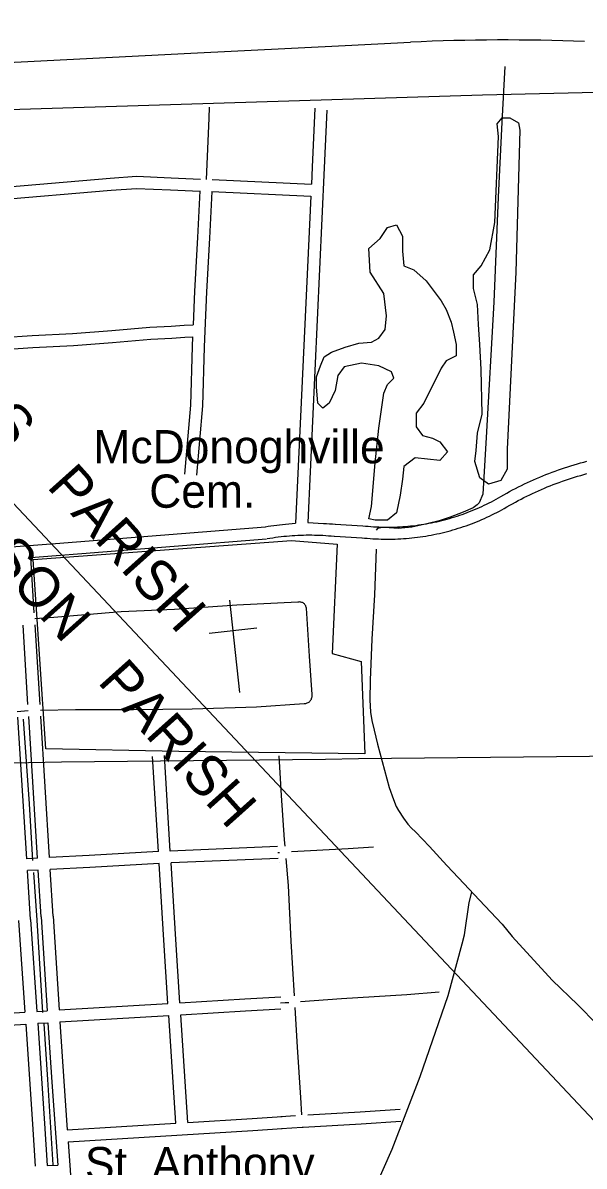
# Model space of a CAD drawing. Extents: x 3677843 to 3715951, y 511991 to 537744.
# Drawn here: x 3687711 to 3689113, y 522520 to 525377 of the extents above; entities that cross this region are included whole.
import ezdxf

# ---------------------------------------------------------------- set-up
doc = ezdxf.new("R2010")
doc.units = 0
for name, color, linetype in [('V-BLDG-IDEN', 7, 'Continuous'), ('V-GRID-MAJR', 7, 'Continuous'), ('V-ROAD-CNTR', 7, 'Continuous'), ('V-SITE-OTLN', 7, 'Continuous'), ('V-SITE-OTLN-IDEN', 7, 'Continuous'), ('V-SITE-VEGE', 7, 'Continuous'), ('V-TOPO-BNDY', 7, 'Continuous'), ('V-TOPO-GNAM-IDEN', 7, 'Continuous'), ('V-TOPO-SHOR', 7, 'Continuous')]:
    doc.layers.add(name, color=color, linetype=linetype)

msp = doc.modelspace()

# ---------------------------------------------------------------- linework, layer by layer
at = {"layer": 'V-GRID-MAJR'}
msp.add_spline([(3682033.6, 523465.9), (3687312.3, 523524.6), (3697869.7, 523644.4)], degree=3, dxfattribs=at)
at = {"layer": 'V-ROAD-CNTR'}
for points in [[(3687004.5, 525244), (3688130.3, 525301.7), (3688516.1, 525320.9), (3688678.9, 525328.8)], [(3689770.8, 525207.3), (3689688.8, 525210.6), (3689500.8, 525212), (3688859.6, 525196.6), (3686680.3, 525129.5)], [(3688176.4, 525166.3), (3688175.7, 525138.9), (3688168.9, 524986.1)], [(3688440.1, 525164.3), (3688433.5, 525016.5), (3688431.5, 524974.4)], [(3688469.9, 525158.9), (3688463.5, 525015.2), (3688422.4, 524128.4)], [(3687634.7, 524964.2), (3687929, 524989.3), (3687994.2, 524993.8), (3688080.9, 524990.4), (3688154.5, 524987)], [(3687636.8, 524934.3), (3687931.3, 524959.3), (3687994.6, 524963.7), (3688079.6, 524960.4), (3688153.1, 524957)], [(3688183.8, 524985.7), (3688431.5, 524974.4)], [(3688152.6, 524957.3), (3688147.1, 524840.6), (3688139.9, 524706.6), (3688136.3, 524622.6)], [(3688182.6, 524955.8), (3688177.1, 524839.1), (3688169.9, 524705.1), (3688165.6, 524607.6), (3688163.9, 524567), (3688159.4, 524420.5), (3688144.5, 524247)], [(3688182.6, 524955.7), (3688430.2, 524944.4)], [(3688430.2, 524944.4), (3688392.3, 524126.9)], [(3687660, 524590.9), (3687734.1, 524596), (3687835, 524601.2), (3687932.7, 524608.7), (3688027.9, 524616.6), (3688081.2, 524619.6), (3688113.8, 524621.4), (3688136.3, 524622.6)], [(3687662.1, 524560.9), (3687735.9, 524566.1), (3687837, 524571.2), (3687935, 524578.8), (3688030, 524586.7), (3688082.9, 524589.6), (3688115.4, 524591.5), (3688134.9, 524592.4)], [(3688134.9, 524592.3), (3688133.9, 524568.1), (3688129.4, 524422.2), (3688114.6, 524249.6)], [(3688905.3, 524193.8), (3688912.4, 524197.9), (3688919.7, 524202), (3688927, 524206), (3688934.4, 524209.9), (3688941.7, 524213.7), (3688949.1, 524217.5), (3688956.6, 524221.2), (3688964.1, 524224.9), (3688971.6, 524228.4), (3688979.2, 524231.9), (3688986.8, 524235.3), (3688994.4, 524238.7), (3689002.1, 524242), (3689009.8, 524245.1), (3689017.5, 524248.3), (3689025.2, 524251.3), (3689033, 524254.3), (3689040.8, 524257.2), (3689048.7, 524260), (3689056.5, 524262.7), (3689064.4, 524265.4), (3689072.3, 524267.9), (3689080.3, 524270.4), (3689088.2, 524272.9), (3689096.2, 524275.2), (3689104.2, 524277.5), (3689112.3, 524279.7), (3689120.3, 524281.8)], [(3688920.2, 524167.8), (3688927.2, 524171.8), (3688934.2, 524175.7), (3688941.3, 524179.6), (3688948.4, 524183.4), (3688955.5, 524187.1), (3688962.6, 524190.7), (3688969.8, 524194.3), (3688977.1, 524197.8), (3688984.3, 524201.3), (3688991.6, 524204.6), (3688999, 524207.9), (3689006.3, 524211.2), (3689013.7, 524214.3), (3689021.1, 524217.4), (3689028.6, 524220.4), (3689036, 524223.3), (3689043.6, 524226.2), (3689051.1, 524229), (3689058.7, 524231.7), (3689066.2, 524234.3), (3689073.9, 524236.9), (3689081.5, 524239.4), (3689089.2, 524241.8), (3689096.8, 524244.1), (3689104.6, 524246.4), (3689112.3, 524248.6), (3689120, 524250.7)], [(3688560.5, 524120.3), (3688567.2, 524119.7), (3688573.8, 524119.1), (3688580.4, 524118.5), (3688587, 524118.1), (3688593.6, 524117.7), (3688600.2, 524117.4), (3688606.8, 524117.2), (3688613.5, 524117.1), (3688620.1, 524117), (3688626.7, 524117), (3688633.3, 524117.1), (3688640, 524117.3), (3688646.6, 524117.6), (3688653.2, 524117.9), (3688659.8, 524118.3), (3688666.4, 524118.8), (3688673, 524119.4), (3688679.6, 524120), (3688686.2, 524120.7), (3688692.7, 524121.5), (3688699.3, 524122.4), (3688705.9, 524123.4), (3688712.4, 524124.4), (3688718.9, 524125.5), (3688725.4, 524126.7), (3688731.9, 524128), (3688738.4, 524129.3), (3688744.9, 524130.7), (3688751.4, 524132.2), (3688757.8, 524133.8), (3688764.2, 524135.4), (3688770.6, 524137.1), (3688777, 524138.9), (3688783.3, 524140.8), (3688789.7, 524142.7), (3688796, 524144.7), (3688802.2, 524146.8), (3688808.5, 524149), (3688814.7, 524151.2), (3688820.9, 524153.5), (3688827.1, 524155.9), (3688833.3, 524158.4), (3688839.4, 524160.9), (3688845.5, 524163.5), (3688851.5, 524166.2), (3688857.6, 524168.9), (3688863.6, 524171.7), (3688869.5, 524174.6), (3688875.5, 524177.6), (3688881.3, 524180.6), (3688887.2, 524183.7), (3688893, 524186.8), (3688898.8, 524190.1), (3688904.6, 524193.4), (3688905.2, 524193.7)], [(3688557.5, 524090.5), (3688564.3, 524089.8), (3688571.2, 524089.2), (3688578.2, 524088.6), (3688585.2, 524088.1), (3688592.1, 524087.8), (3688599.1, 524087.4), (3688606.1, 524087.2), (3688613, 524087.1), (3688620, 524087), (3688627, 524087), (3688634, 524087.2), (3688640.9, 524087.3), (3688647.9, 524087.6), (3688654.9, 524088), (3688661.8, 524088.4), (3688668.8, 524088.9), (3688675.7, 524089.5), (3688682.7, 524090.2), (3688689.6, 524090.9), (3688696.5, 524091.8), (3688703.5, 524092.7), (3688710.4, 524093.7), (3688717.2, 524094.8), (3688724.1, 524096), (3688731, 524097.2), (3688737.8, 524098.5), (3688744.7, 524100), (3688751.5, 524101.4), (3688758.3, 524103), (3688765.1, 524104.7), (3688771.8, 524106.4), (3688778.5, 524108.2), (3688785.3, 524110.1), (3688792, 524112), (3688798.6, 524114.1), (3688805.3, 524116.2), (3688811.9, 524118.4), (3688818.5, 524120.7), (3688825, 524123.1), (3688831.6, 524125.5), (3688838.1, 524128), (3688844.6, 524130.6), (3688851, 524133.2), (3688857.4, 524136), (3688863.8, 524138.8), (3688870.2, 524141.7), (3688876.5, 524144.6), (3688882.8, 524147.7), (3688889, 524150.8), (3688895.2, 524154), (3688901.4, 524157.2), (3688907.5, 524160.6), (3688913.6, 524164), (3688919.6, 524167.4), (3688920.3, 524167.8)], [(3687670.8, 524066.9), (3687791.9, 524076), (3688317.3, 524118.1)], [(3688316.1, 524117.9), (3688323.2, 524119.1), (3688330.5, 524120.2), (3688337.7, 524121.3), (3688345, 524122.2), (3688352.3, 524123.1), (3688359.6, 524123.9), (3688366.9, 524124.6), (3688392.3, 524126.9)], [(3688422.4, 524128.4), (3688462.1, 524126.5), (3688469.4, 524126.1), (3688476.7, 524125.6), (3688484, 524125), (3688491.3, 524124.4), (3688491.8, 524124.3)], [(3688491.1, 524124.4), (3688559.9, 524120.4)], [(3687857.9, 524051.2), (3688319.7, 524088.2)], [(3688321, 524088.3), (3688328, 524089.5), (3688334.9, 524090.6), (3688341.8, 524091.6), (3688348.8, 524092.5), (3688355.7, 524093.3), (3688362.7, 524094.1), (3688369.6, 524094.8), (3688376.6, 524095.4), (3688383.6, 524095.9), (3688390.6, 524096.4), (3688397.5, 524096.7), (3688404.5, 524097), (3688411.5, 524097.3), (3688418.5, 524097.4), (3688425.5, 524097.5), (3688432.5, 524097.4), (3688439.5, 524097.3), (3688446.5, 524097.2), (3688453.5, 524096.9), (3688460.5, 524096.6), (3688467.5, 524096.2), (3688474.5, 524095.7), (3688481.4, 524095.1), (3688488.4, 524094.5), (3688488.8, 524094.5)], [(3688489.4, 524094.4), (3688558.1, 524090.4)], [(3687730.6, 524041.3), (3687794.2, 524046.1), (3687857.9, 524051.2)], [(3687739.2, 523902.7), (3687730.6, 524041.3)], [(3687754.3, 523659.9), (3687841.9, 523661.6), (3687987.1, 523661.5), (3688133.8, 523663), (3688294.7, 523668.3), (3688413.5, 523676.2), (3688415.5, 523676.3), (3688417.5, 523676.5), (3688419.5, 523677), (3688421.4, 523677.7), (3688423.2, 523678.5), (3688424.9, 523679.6), (3688426.6, 523680.8), (3688428, 523682.2), (3688429.4, 523683.7), (3688430.5, 523685.4), (3688431.5, 523687.2), (3688432.3, 523689), (3688432.9, 523691), (3688433.3, 523692.9), (3688433.5, 523695), (3688433.5, 523697), (3688433.3, 523699), (3688426.9, 523794.5), (3688419, 523914.8), (3688418.7, 523916.7), (3688418.1, 523918.6), (3688417.4, 523920.4), (3688416.4, 523922.1), (3688415.3, 523923.6), (3688414, 523925.1), (3688412.5, 523926.4), (3688410.9, 523927.5), (3688409.2, 523928.4), (3688407.4, 523929.1), (3688405.5, 523929.6), (3688403.6, 523929.9), (3688401.6, 523930), (3688399.7, 523929.8), (3688397.8, 523929.5), (3688245.1, 523922.1), (3688089.3, 523911.2), (3687956, 523905), (3687788.3, 523891.4), (3687740.4, 523888.2)], [(3687723.4, 523673.4), (3687711.1, 523871.9)], [(3687753.5, 523674.1), (3687741.1, 523873)], [(3687696.8, 523656.6), (3687723.9, 523658.5)], [(3687720.3, 523288.4), (3687697.7, 523641.9)], [(3687747.3, 523289.8), (3687725.3, 523643.7)], [(3687777.3, 523291.4), (3687755.3, 523644.3)], [(3688049.2, 523306), (3688034.3, 523544.1)], [(3688079.1, 523307.6), (3688064.3, 523546)], [(3688350.2, 523545.5), (3688356, 523446.6), (3688363.7, 523335.8), (3688365.1, 523320)], [(3688049.2, 523306), (3687876.6, 523296.5), (3687777.3, 523291.4)], [(3688347.1, 523319.1), (3688079.1, 523307.6)], [(3688381.6, 523306), (3688523.8, 523313.9), (3688586.7, 523318.1)], [(3687747.3, 523289.8), (3687720.3, 523288.4)], [(3688348.8, 523289.1), (3688081, 523277.7)], [(3688103.2, 522928.6), (3688092.9, 523086.5), (3688081, 523277.7)], [(3688347.9, 523304.1), (3688352.3, 523304.3)], [(3688351.2, 523278.1), (3688351.2, 523278.1)], [(3688351.2, 523278.1), (3688351.2, 523278.1)], [(3688367.9, 523289), (3688373.9, 523221.8), (3688380.3, 523082.3), (3688388.6, 522945.9)], [(3687749.2, 523259.9), (3687722.2, 523258.5)], [(3687730, 523136.1), (3687722.2, 523258.5)], [(3687756.4, 523143), (3687749.2, 523259.9)], [(3688051, 523276.1), (3687878.2, 523266.6), (3687779.1, 523261.5)], [(3687786.4, 523144.9), (3687779.1, 523261.5)], [(3688073.2, 522926.7), (3688063, 523084.6), (3688051, 523276.1)], [(3687700, 523134.1), (3687715.7, 522905.1)], [(3687730, 523136.1), (3687745.7, 522906.9)], [(3687756.4, 523143), (3687771.4, 522908.4)], [(3687786.4, 523144.9), (3687801.3, 522910.3)], [(3688103.2, 522928.6), (3688265.5, 522938.4), (3688355.1, 522943.5)], [(3688404.3, 522931.4), (3688506.7, 522938.8), (3688669.7, 522949.1), (3688750.9, 522955.7)], [(3687745.7, 522906.9), (3687771.4, 522908.4)], [(3687801.3, 522910.3), (3688073.2, 522926.7)], [(3688105.1, 522898.6), (3688267.3, 522908.5), (3688355.4, 522913.5)], [(3688354.5, 522928), (3688365.9, 522928.7), (3688374.9, 522929.3)], [(3688390.3, 522916.6), (3688396.1, 522817.6), (3688404.5, 522691.5), (3688406.5, 522648.4)], [(3686535.1, 522826.8), (3686795.9, 522844.4), (3687220.5, 522870.4), (3687579.8, 522896.8), (3687715.7, 522905.1)], [(3687747.7, 522877), (3687773.3, 522878.5)], [(3687747.7, 522877), (3687764.9, 522626.6), (3687771.5, 522521.6)], [(3687773.3, 522878.5), (3687782.7, 522730.2), (3687797.8, 522522.9)], [(3687803.2, 522880.3), (3688075.2, 522896.8)], [(3687803.2, 522880.3), (3687812.7, 522732.2), (3687821.5, 522610.5)], [(3688092.8, 522627.4), (3688075.2, 522896.8)], [(3688122.7, 522629.2), (3688105.1, 522898.6)], [(3686537, 522796.9), (3686797.9, 522814.4), (3687222.5, 522840.5), (3687581.8, 522866.9), (3687717.8, 522875.1)], [(3687717.8, 522875.1), (3687735, 522624.7), (3687741.5, 522520.1)], [(3688422.4, 522648.2), (3688553.8, 522655.5), (3688653.5, 522662.4)], [(3687821.5, 522610.5), (3688092.8, 522627.4)], [(3688122.7, 522629.2), (3688283.5, 522639.2), (3688358.5, 522644)], [(3688355.5, 522644.1), (3688392.3, 522646.4)], [(3688357.3, 522614.1), (3688408.2, 522617.3), (3688411.2, 522617.5), (3688555.7, 522625.5), (3688655.5, 522632.5)], [(3687823.7, 522580.6), (3688285.4, 522609.3), (3688358.9, 522614)], [(3687823.7, 522580.6), (3687834, 522439.2)], [(3687771.5, 522521.6), (3687797.8, 522522.9)]]:
    msp.add_lwpolyline(points, dxfattribs=at)
msp.add_arc((3688914.3, 520521.4), 4813.2, 87.6216, 92.8029, dxfattribs=at)
at = {"layer": 'V-SITE-OTLN'}
for p, q in [((3688252.9, 523703.9), (3688227.5, 523934.7)), ((3688295.6, 523864.4), (3688176.3, 523851.2))]:
    msp.add_line(p, q, dxfattribs=at)
msp.add_lwpolyline([(3688565.1, 523550.8), (3688100.3, 523556.6), (3687768.2, 523562.7), (3687736.7, 524035.9), (3688382.2, 524083.3), (3688495.7, 524074.6), (3688483.9, 523801.3), (3688555.9, 523781.2)], close=True, dxfattribs=at)
at = {"layer": 'V-SITE-VEGE'}
for points in [[(3688889.8, 524878.7), (3688899.2, 525093.6), (3688896.1, 525124.7), (3688908.5, 525140.3), (3688927.2, 525140.3), (3688949, 525127.8), (3688952.1, 525109.2), (3688942.8, 524754.1), (3688921, 524311.8), (3688921, 524262), (3688905.4, 524233.9), (3688874.3, 524224.6), (3688852.5, 524240.2), (3688840, 524280.7), (3688843.1, 524308.7), (3688846.3, 524352.3), (3688858.7, 524399), (3688855.6, 524511.1), (3688852.5, 524573.4), (3688849.4, 524623.3), (3688846.3, 524673.1), (3688836.9, 524713.6), (3688836.9, 524747.9), (3688855.6, 524769.7), (3688877.4, 524810.2)], [(3688718.6, 524732.3), (3688756, 524682.4), (3688768.4, 524660.6), (3688780.9, 524629.5), (3688787.1, 524604.6), (3688793.3, 524573.4), (3688793.3, 524545.4), (3688768.4, 524532.9), (3688756, 524514.3), (3688712.4, 524427), (3688693.7, 524402.1), (3688693.7, 524367.9), (3688709.3, 524346.1), (3688734.2, 524339.8), (3688752.9, 524330.5), (3688771.5, 524305.6), (3688752.9, 524283.8), (3688721.7, 524286.9), (3688690.6, 524290), (3688662.6, 524268.2), (3688659.5, 524237), (3688653.3, 524196.6), (3688643.9, 524153), (3688622.1, 524134.3), (3688591, 524134.3), (3688575.4, 524137.4), (3688581.7, 524168.5), (3688591, 524277.5), (3688600.3, 524364.7), (3688612.8, 524452), (3688622.1, 524473.8), (3688637.7, 524489.3), (3688631.5, 524504.9), (3688600.3, 524520.5), (3688556.8, 524526.7), (3688513.2, 524517.4), (3688497.6, 524495.6), (3688491.4, 524458.2), (3688475.8, 524427), (3688460.3, 524414.6), (3688447.8, 524427), (3688444.7, 524467.5), (3688444.7, 524492.5), (3688454, 524520.5), (3688463.4, 524542.3), (3688482, 524554.7), (3688516.3, 524567.2), (3688550.5, 524576.5), (3688581.7, 524579.7), (3688600.3, 524589), (3688615.9, 524610.8), (3688619, 524645.1), (3688612.8, 524701.1), (3688578.5, 524754.1), (3688575.4, 524813.3), (3688603.4, 524838.2), (3688622.1, 524866.2), (3688643.9, 524872.4), (3688659.5, 524844.4), (3688659.5, 524807), (3688662.6, 524769.7), (3688687.5, 524760.3)]]:
    msp.add_lwpolyline(points, close=True, dxfattribs=at)
at = {"layer": 'V-TOPO-BNDY'}
msp.add_line((3686105, 525857.1), (3690694, 520979.3), dxfattribs=at)
at = {"layer": 'V-TOPO-SHOR'}
for points in [[(3688915, 525268.1), (3688907.1, 525128.9), (3688898.2, 524941.5), (3688887.5, 524679.7), (3688868.3, 524340.9), (3688860, 524199.3), (3688850.5, 524178.2), (3688845.8, 524172.4), (3688835.6, 524165.3), (3688810.5, 524154.5), (3688778.4, 524141.7), (3688750.6, 524132.4), (3688719.7, 524125.1), (3688682.5, 524116.6), (3688648.4, 524113.6), (3688626.1, 524115.2), (3688608.9, 524116), (3688596.8, 524113.7), (3688593.2, 524109.1)], [(3688593.7, 524062.1), (3688589, 523947.9), (3688582.8, 523836.9), (3688578.9, 523734.8), (3688577.6, 523685.6), (3688579.4, 523654.3), (3688582.9, 523633.5), (3688588.6, 523609.3), (3688597.1, 523574.4), (3688626.1, 523466.4), (3688636.5, 523436.3), (3688643.1, 523419), (3688649.7, 523408.9), (3688661.4, 523390), (3688672.7, 523374.8), (3688682, 523364.9), (3688691.4, 523355.5), (3688726.8, 523318.6), (3688769.7, 523271.6), (3688798.9, 523240.2), (3688865.1, 523170.4), (3688908, 523124.8), (3688933.3, 523094.3), (3689033.4, 522985.2), (3689097.7, 522923.2), (3689192.4, 522826.7)], [(3687711.3, 523637.5), (3687726.7, 523425.2), (3687735.1, 523283.6)], [(3687737.4, 523253.9), (3687745.7, 523134.9), (3687759.6, 522904.2)], [(3688475.3, 522216.9), (3688547.2, 522366.9), (3688633.8, 522562.7), (3688703.5, 522743.7), (3688773.2, 522946.6), (3688808.6, 523075.6), (3688814.5, 523098.3), (3688816.5, 523115.6), (3688823, 523161.8), (3688826.2, 523179.1), (3688832.8, 523204.4)], [(3687762.7, 522875.7), (3687772.2, 522736.2), (3687785.7, 522523.7)]]:
    msp.add_lwpolyline(points, dxfattribs=at)

# ---------------------------------------------------------------- texts
at = {"layer": 'V-BLDG-IDEN'}
msp.add_text('St. Anthony', height=83, dxfattribs=at).set_placement((3687865.8, 522484.8))
at = {"layer": 'V-SITE-OTLN-IDEN'}
for s, p in [('McDonoghville', (3687886.9, 524276.6)), ('Cem.', (3688026.4, 524165.5))]:
    msp.add_text(s, height=83, dxfattribs=at).set_placement(p)
at = {"layer": 'V-TOPO-GNAM-IDEN'}
for s, rotation, p in [('ORLEANS', 312.2037, (3687246.2, 524782.4)), ('JEFFERSON', 311.855, (3687282.8, 524415.6)), ('PARISH', 311.855, (3687768.4, 524217.5)), ('PARISH', 311.855, (3687895.2, 523729.3))]:
    msp.add_text(s, height=100, rotation=rotation, dxfattribs=at).set_placement(p)

doc.saveas('drawing.dxf')
